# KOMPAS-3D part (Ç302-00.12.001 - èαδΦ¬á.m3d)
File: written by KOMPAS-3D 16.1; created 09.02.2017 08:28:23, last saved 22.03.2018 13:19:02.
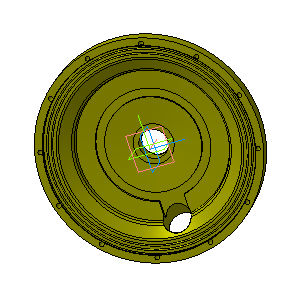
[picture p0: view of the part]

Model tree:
1. Эскиз:24
2. Операция вращения:2
     Угол 1 = 360
3. Эскиз:26
4. Вырезать элемент выдавливания:1
     Расстояние 1 = 19
5. Массив по концентрической сетке:2  (with: Вырезать элемент выдавливания:1, Эскиз:26)  (12 pattern instances)
     Геометрический массив = 11; Шаг 2 = 360
6. Фаска:1
     Угол = 45; Длина 1 = 0.5; Длина 2 = 0.5
7. Скругление:3
     Радиус = 6
8. Эскиз:29
9. Вырезать элемент выдавливания:2
     Расстояние 1 = 47.5
10. Эскиз:30
11. Вырезать элемент выдавливания:3
     Расстояние 1 = 51.5
12. Фаска:2
     Угол = 45; Длина 1 = 0.5; Длина 2 = 0.5
13. Эскиз:32
14. Вырезать элемент выдавливания:4
     Расстояние 1 = 51.5
15. Эскиз:33
16. Вырезать элемент вращения:1
     Угол 1 = 360
17. Эскиз:35
18. Операция выдавливания:1
     Толщина стенки 1 = 2; Расстояние 1 = 1
19. Скругление:4
     Радиус = 1
20. Фаска:3
     Угол = 45; Длина 1 = 1; Длина 2 = 1
21. Эскиз:36
22. Вырезать элемент выдавливания:6
     Расстояние 1 = 5
23. Скругление:5
     Радиус = 0.5
24. Сечение поверхностью:1  (labels: А302-00.12.001; Полипропилен  ГОСТ 26996-86)

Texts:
  Линейный размер с обрывом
